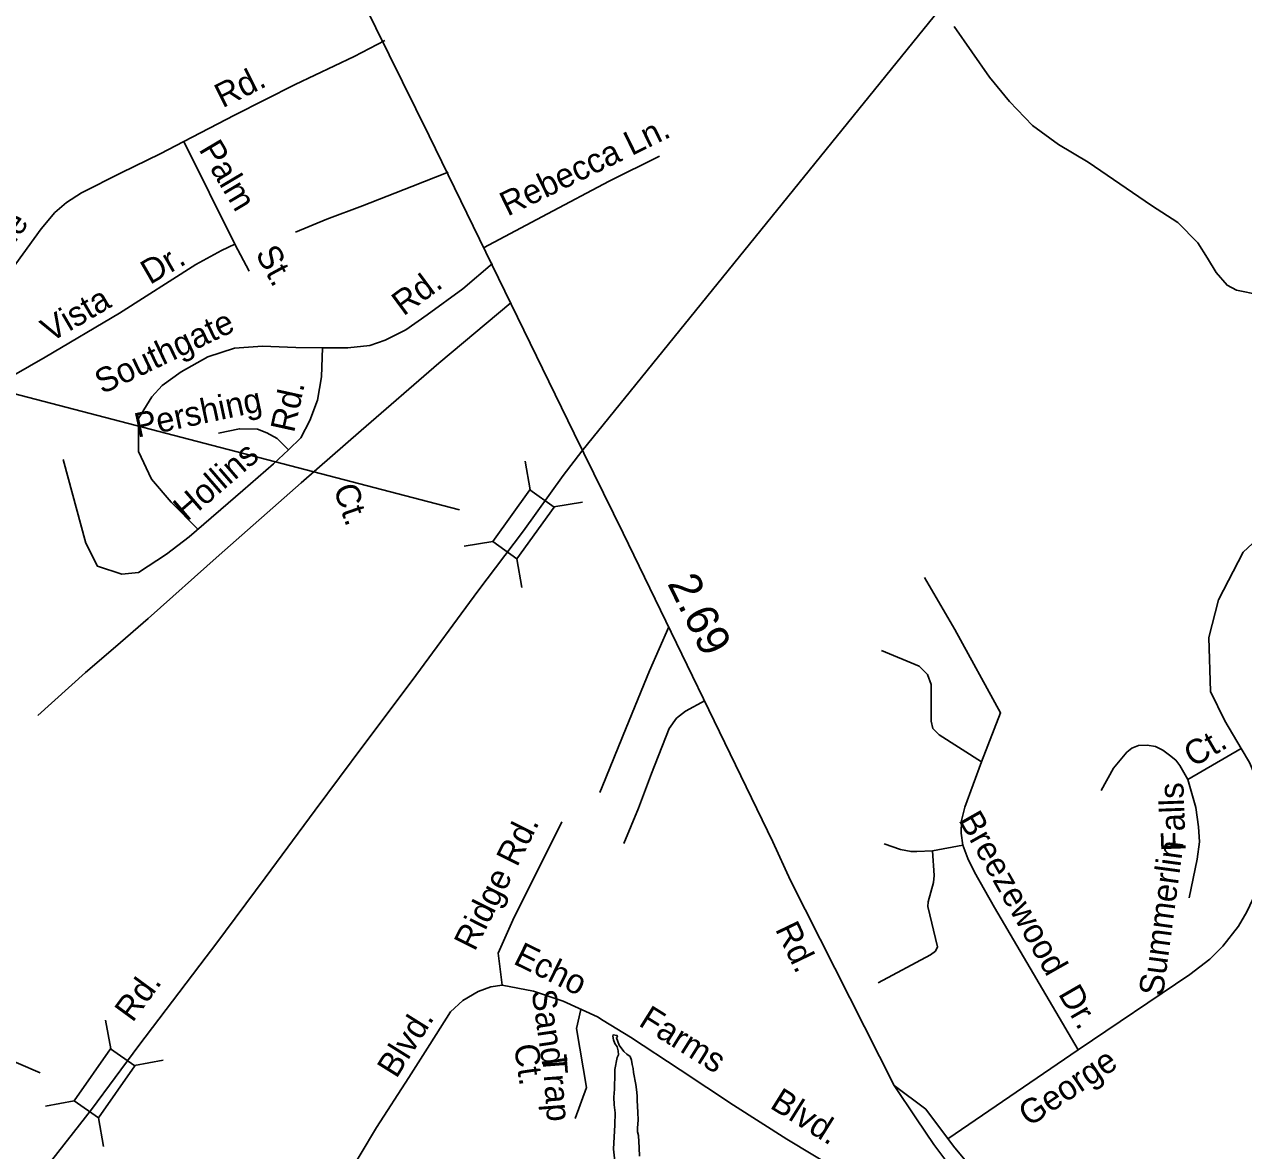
# Model space of a CAD drawing. Extents: x 2290055 to 2389491, y 66597 to 237875.
# Drawn here: x 2322939 to 2327683, y 153914 to 158294 of the extents above; entities that cross this region are included whole.
import ezdxf

# ---------------------------------------------------------------- set-up
doc = ezdxf.new("R2010")
doc.units = 0
for name, color, linetype in [('Exist Hydrographic Pond Under 1500 Sq Ft', 7, 'Continuous'), ('Exist Road Non-System Structure Non-Sys Other Number Label', 7, 'Continuous'), ('Exist Road Non-System Type 51', 7, 'Continuous'), ('Exist Road Non-System Type 51 Label', 7, 'Continuous'), ('Exist Road Primary US Divided Attributed', 7, 'Continuous'), ('Exist Road Primary US Label', 7, 'Continuous'), ('Exist Road Primary US Mileage Hundredths English Label', 7, 'Continuous'), ('Exist Road Primary US UnDivided 4 Lane Attributed', 7, 'Continuous')]:
    doc.layers.add(name, color=color, linetype=linetype)

msp = doc.modelspace()

# ---------------------------------------------------------------- linework, layer by layer
at = {"layer": 'Exist Hydrographic Pond Under 1500 Sq Ft'}
msp.add_lwpolyline([(2325235.7, 153872.6), (2325231, 153919.8), (2325236.5, 154013.4), (2325237, 154060.5), (2325234.2, 154091.1), (2325233, 154121.8), (2325235, 154152.2), (2325235.7, 154214.4), (2325236.7, 154229.6), (2325245.5, 154275.2), (2325250, 154286.3), (2325249, 154301.4), (2325245.2, 154317.1), (2325236.5, 154330), (2325230.5, 154344.1), (2325228.5, 154359.1), (2325229.5, 154363.4), (2325244.5, 154361.5), (2325246, 154358), (2325242.2, 154352.5), (2325253, 154323.8), (2325271.2, 154299), (2325283, 154288.6), (2325295.5, 154279.3), (2325301.5, 154265.4), (2325303.5, 154249.1), (2325307.2, 154232.4), (2325309, 154217.4), (2325318, 154171.2), (2325322, 154140.4), (2325323, 154124.1), (2325323, 154109), (2325326.2, 154062.6), (2325327, 154031.8), (2325324.7, 154001.9), (2325325, 153986.8), (2325328.5, 153972.1), (2325331.2, 153924.3), (2325332, 153892.5)], dxfattribs=at)
at = {"layer": 'Exist Road Non-System Structure Non-Sys Other Number Label'}
for p, q in [((2324631.3, 156406.7), (2322273.3, 157021.4)), ((2324906.4, 156483.9), (2324888, 156595.5)), ((2324998.3, 156417.9), (2325110, 156436.2)), ((2324649.7, 156264.4), (2324761.4, 156282.8)), ((2324873.8, 156103.6), (2324855.5, 156215.3)), ((2322999.8, 154216.2), (2321362, 154918.1)), ((2323274.8, 154309.7), (2323254.9, 154421.2)), ((2323367.6, 154245), (2323479, 154264.8)), ((2323021, 154087), (2323132.4, 154106.8)), ((2323247.2, 153929.1), (2323227.4, 154040.5))]:
    msp.add_line(p, q, dxfattribs=at)
for points in [[(2324761.4, 156282.8), (2324905.9, 156484.2), (2325000, 156416.7), (2324855.5, 156215.3)], [(2323132.4, 154106.8), (2323274.3, 154310.1), (2323369.3, 154243.8), (2323227.4, 154040.5)]]:
    msp.add_lwpolyline(points, close=True, dxfattribs=at)
at = {"layer": 'Exist Road Non-System Type 51'}
for points in [[(2325107.4, 156633.7), (2327661.6, 159787.7)], [(2328476.6, 157085.3), (2328359.4, 157110.6), (2328147.9, 157148.2), (2327949.9, 157200.4), (2327744.1, 157242.1), (2327655.4, 157260.9), (2327618.5, 157279.5), (2327576.5, 157329.7), (2327542.5, 157384.5), (2327504, 157445), (2327427, 157524), (2327324.3, 157589.8), (2327077.4, 157758.3), (2326962.8, 157827.6), (2326861.7, 157901.7), (2326772.1, 157994), (2326694.1, 158089), (2326556.4, 158285.8)], [(2324341.9, 158232), (2324222.2, 158169.5), (2323992.6, 158060.3), (2323757, 157941), (2323559.2, 157839)], [(2323559.2, 157839), (2323466.9, 157791.4), (2323315.9, 157717.5), (2323160.8, 157639.2), (2323102.3, 157601.1), (2323057.8, 157563.2), (2323004.2, 157499.1), (2322905.6, 157362.9), (2322767.2, 157169.4), (2322628.7, 156978.1), (2322539.9, 156850.6), (2322483.2, 156775.4)], [(2323559.2, 157839), (2323757.8, 157439.4), (2323813.1, 157334.9)], [(2325409.9, 157782.3), (2325213.9, 157684.6), (2324974.7, 157557), (2324725.9, 157425)], [(2323993.3, 157486), (2324115.3, 157537.1), (2324255.1, 157588.6), (2324446.4, 157664.1), (2324588.3, 157719.6)], [(2322494, 156744.4), (2322502.3, 156738.8), (2322524.8, 156725.9), (2322568.4, 156735.5), (2322722.5, 156829.6), (2323020.1, 156999.5), (2323309.3, 157170.8), (2323606, 157360.7), (2323706.4, 157414.3)], [(2323706.4, 157414.3), (2323757.8, 157439.4)], [(2324099, 157036.3), (2324197.2, 157035.9), (2324282.8, 157045.5), (2324342.1, 157065.6), (2324422.5, 157106.8), (2324506.2, 157164.3), (2324644.3, 157265.9), (2324760.2, 157364.4)], [(2323293.2, 155873.6), (2323420.3, 155982.8), (2323696.7, 156230.1), (2324015.8, 156510.5), (2324249.9, 156714.1), (2324551.7, 156976.1), (2324832.2, 157211.3)], [(2324099, 157036.3), (2323994.9, 157038.1), (2323864.8, 157042.8), (2323757.1, 157034.6), (2323652.1, 157000.6), (2323548.4, 156942.3), (2323474.7, 156889.5), (2323434.4, 156845.9), (2323382.4, 156760.8)], [(2323966.7, 156638.9), (2324014.7, 156686.7), (2324050.1, 156754.1), (2324079.2, 156833.3), (2324095.6, 156923.9), (2324099, 157036.3)], [(2323382.4, 156760.8), (2323382.4, 156633.4), (2323433.3, 156525), (2323509.7, 156435.8), (2323614.4, 156331)], [(2323966.7, 156638.9), (2323923, 156683.1), (2323882.1, 156705.4), (2323845.4, 156720), (2323775.4, 156721.2), (2323694.1, 156703.9)], [(2323492.4, 156233.2), (2323580, 156301.3), (2323788.8, 156481.8), (2323908.8, 156584.4), (2323966.7, 156638.9)], [(2323492.4, 156233.2), (2323382.4, 156161.8), (2323318.7, 156155.4), (2323223.2, 156187.3), (2323178.6, 156276.5), (2323089.4, 156601.5)], [(2325107.4, 156633.7), (2325035, 156539), (2324881.4, 156324.8), (2324807.8, 156228.1)], [(2327038.9, 154305.5), (2327473.8, 154598.9), (2327550.7, 154658.2), (2327602.3, 154708.8), (2327662.7, 154786.8), (2327695.6, 154842.9), (2327729, 154914.1), (2327758.7, 155018.3), (2327769.9, 155129.9), (2327756.9, 155274.9), (2327737.6, 155346.9), (2327706, 155423.8), (2327673.8, 155477.1), (2327609.4, 155585), (2327553.6, 155699), (2327546.8, 155909.5), (2327585, 156056), (2327680.6, 156240.8), (2327858.9, 156406.5)], [(2324807.8, 156228.1), (2324702.6, 156089.7), (2324448.2, 155741.6), (2324260.2, 155491.9), (2324070, 155238.3), (2323876.3, 154974.6), (2323683.5, 154716.8)], [(2327038.9, 154305.5), (2326713.4, 154859.5), (2326635.3, 154997.2), (2326609.3, 155049.3), (2326590.7, 155101.3), (2326583.3, 155148.5), (2326584.5, 155198.1), (2326598.3, 155249), (2326662.6, 155426.2), (2326736.9, 155616), (2326559.1, 155940.2), (2326441.6, 156143.3)], [(2325446.5, 155951.1), (2325371.2, 155780), (2325279.9, 155558.2), (2325186.9, 155328.7), (2325177.3, 155306.4)], [(2322991.2, 155605.8), (2323176.5, 155773.3), (2323293.2, 155873.6)], [(2326274.3, 155858.3), (2326420.3, 155797.7), (2326452.3, 155765.7), (2326466.6, 155726.5), (2326466.6, 155583.9), (2326473.7, 155555.4), (2326498.6, 155530.5), (2326662.6, 155426.2)], [(2325587.8, 155664.5), (2325511.3, 155623.4), (2325476.3, 155596.1), (2325448.1, 155555), (2325378.9, 155380.3), (2325328.4, 155246), (2325271.8, 155107.9)], [(2327466.2, 155356.8), (2327434, 155411.4), (2327418.5, 155432.4), (2327394.4, 155452.3), (2327369, 155470.9), (2327339.8, 155485.8), (2327307, 155490.7), (2327274.2, 155489.5), (2327247.5, 155479.6), (2327227.7, 155463.4), (2327176.3, 155401.4), (2327127.9, 155314.6)], [(2327673.8, 155477.1), (2327466.2, 155356.8)], [(2327466.2, 155356.8), (2327497.2, 155247.7), (2327507.1, 155173.3), (2327510.9, 155115), (2327502.2, 155046.8), (2327470.4, 154896.3)], [(2324797.4, 154556.8), (2324782, 154682.2), (2324839.3, 154809.6), (2325030.3, 155192)], [(2326471.7, 155080.3), (2326479.2, 154983.5), (2326476.7, 154956.3), (2326455.6, 154881.8), (2326454.4, 154863.2), (2326492.2, 154705.8), (2326483.5, 154689.6), (2326464.9, 154674.8), (2326260.4, 154565.6)], [(2326284.6, 155106.3), (2326347.8, 155085.2), (2326388.7, 155076.5), (2326411, 155076.5), (2326471.7, 155080.3), (2326590.7, 155101.3)], [(2323683.5, 154716.8), (2323646.6, 154667.5), (2323383.9, 154323), (2323199.8, 154073.5), (2323022.7, 153846.6), (2322850.2, 153601.5)], [(2324113.2, 153691.5), (2324181.4, 153790.4), (2324308.9, 154003.5), (2324435.4, 154198.5), (2324516.4, 154325.8), (2324597.3, 154453.1), (2324645.5, 154497), (2324704.1, 154533.1), (2324753.6, 154551.1), (2324797.4, 154556.8), (2324920.4, 154533.8), (2325035.8, 154494.3), (2325168.2, 154433.6), (2325191.4, 154419.4)], [(2325081.3, 154038.6), (2325125.8, 154159.7), (2325087.6, 154389.1), (2325104.1, 154463)], [(2325191.4, 154419.4), (2325297.3, 154354.7), (2325490.4, 154228.1), (2325698, 154090.3), (2325905.4, 153958.3), (2326114.5, 153832.7), (2326208.9, 153770.5)], [(2326532, 153959.3), (2327038.9, 154305.5)]]:
    msp.add_lwpolyline(points, dxfattribs=at)
at = {"layer": 'Exist Road Primary US Divided Attributed'}
for points in [[(2326323.2, 154166.7), (2326409.4, 154037.1), (2326477.6, 153937.8), (2326581.9, 153797.4), (2326702.6, 153653.8), (2326921.5, 153390.7), (2327179.6, 153078), (2327383.3, 152817.2), (2327475.4, 152716.4), (2327513.3, 152672.1), (2327880.5, 152228.9), (2328302.8, 151710.6), (2328538.7, 151433.5), (2328702.8, 151223.1), (2329000.3, 150867.3), (2329140.5, 150691.1), (2329272.1, 150532), (2329419.1, 150354.1), (2329468.7, 150295.9), (2329626.9, 150087.6), (2329909.4, 149732)], [(2329958.4, 149778.9), (2329820.9, 149959), (2329650.9, 150147.6), (2329473.8, 150379.8), (2329328.5, 150552.5), (2329027.6, 150932.3), (2328882.3, 151105), (2328041.2, 152129.7), (2327827.5, 152379.4), (2327347.1, 152964.4), (2326950.5, 153453.6), (2326553.9, 153930.9), (2326446.7, 154074.4), (2326323.2, 154166.7)]]:
    msp.add_lwpolyline(points, dxfattribs=at)
at = {"layer": 'Exist Road Primary US UnDivided 4 Lane Attributed'}
msp.add_lwpolyline([(2326323.2, 154166.7), (2325919.8, 154964.8), (2325850.8, 155114.4), (2325269, 156315.9), (2325078.2, 156702.5), (2324513.4, 157860.8), (2323787.5, 159333.1), (2322848.6, 161249.8), (2322274.2, 162403.6)], dxfattribs=at)

# ---------------------------------------------------------------- texts
at = {"layer": 'Exist Road Non-System Type 51 Label'}
for s, rotation, p in [('Rd.', 26.562, (2323709.8, 157967.3)), ('Rebecca Ln.', 26.037, (2324819, 157546.3)), ('Palm', 300.648, (2323615.7, 157808.6)), ('Sunnyvale', 54.4312, (2322614.4, 157040.4)), ('Dr.', 30.0919, (2323427.5, 157280.5)), ('St.', 298.435, (2323835.9, 157403.4)), ('Rd.', 36.5123, (2324413.9, 157157.6)), ('Vista', 30.348, (2323039.8, 157055.5)), ('Southgate', 25.5078, (2323241.7, 156854.7)), ('Rd.', 77.5919, (2323988, 156702.9)), ('Pershing', 12.0234, (2323378.7, 156686.7)), ('Hollins', 40.8501, (2323570.1, 156357.7)), ('Ct.', 289.1424, (2324140.1, 156489.8)), ('Ct.', 30.215, (2327485.8, 155402.7)), ('Falls', 92.02, (2327457.6, 155079)), ('Breezewood', 299.5756, (2326571.4, 155200)), ('Ridge Rd.', 63.3774, (2324691.1, 154685.1)), ('Summerlin', 82.3059, (2327368.7, 154511.7)), ('Echo', 333.622, (2324837, 154642.5)), ('Rd.', 53.8048, (2323359.9, 154409)), ('Dr.', 300.0252, (2326959.4, 154523.5)), ('Sand', 278.2492, (2324912, 154534.3)), ('Farms', 327.9142, (2325324.4, 154402.3)), ('Blvd.', 57.9564, (2324386.2, 154190.8)), ('Ct.', 278.2492, (2324843.6, 154322.8)), ('Trap', 274.2815, (2324953.7, 154284.4)), ('George', 33.8955, (2326848.2, 154004.1)), ('Blvd.', 327.9142, (2325835.3, 154082))]:
    msp.add_text(s, height=95, rotation=rotation, dxfattribs=at).set_placement(p)
at = {"layer": 'Exist Road Primary US Label'}
msp.add_text('Rd.', height=95, rotation=295.6719, dxfattribs=at).set_placement((2325858.7, 154775.4))
at = {"layer": 'Exist Road Primary US Mileage Hundredths English Label'}
msp.add_text('2.69', height=125, rotation=296.2515, dxfattribs=at).set_placement((2325438.9, 156119.7))

doc.saveas('drawing.dxf')
